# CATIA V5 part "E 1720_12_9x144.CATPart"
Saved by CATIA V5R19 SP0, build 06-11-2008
Nomenclature: E 1720_12_9x144
Description: PART-E 1720_12_9x144-DESC
Property "Hersteller": "Meusburger"
Property "Material": "1.2210"
Property "Bestellnummer": "E 1720/12/9x144"
Property "Teilenummer": "E 1720/12/9x144"
Property "Beschreibung": "Auswerferhülse gehärtet _ Sleeve ejector, through-hardened"
Material "Steel": density 7860 kg/m3, Young's modulus 2e+11 Pa, Poisson ratio 0.266, thermal expansion 1.17e-05 1/K
Bounding box of the stored display mesh (mm): x -10 to 10, y -10 to 10, z 0 to 144
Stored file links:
  G:\UTB\Kombinované\Bakalářská práce\Catia\FORMA\E 1720_12_9x144.CATPart
  D:\Aplikace\CATIA\Nová složka\win_b64\startup\materials\Catalog.CATMaterial
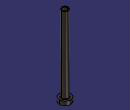
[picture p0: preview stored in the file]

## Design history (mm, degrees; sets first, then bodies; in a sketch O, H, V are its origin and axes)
Body1 "E 1720_12_9x144" (main body)
  Solid1: solid without history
